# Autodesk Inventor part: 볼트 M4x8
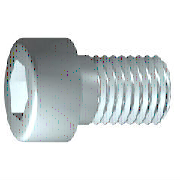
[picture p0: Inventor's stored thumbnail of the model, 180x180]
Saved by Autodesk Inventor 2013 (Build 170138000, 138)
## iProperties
Created: 2012-02
Part Number: 볼트 M4x8
Material: 스테인리스강
Description: 6각 소켓 머리 캡 나사
Document SubType Name: Modeling
Standard: ISO 4762
Designer: mduedu
Standard Revision: Fourth edition 2004-03-01
Standards Organization: ISO
Language: ko-KR
Size Designation: M4 x 8
Categories: <MemberInstance><Categories><Category DisplayName="조임쇠" InternalName="e4da775c-781d-43d5-af7c-5136215cf5a6" Mnemonic="FSTN"><Category DisplayName="볼트" InternalN
Density: 7.75 g/cm^3
Mass: 1.81382 g
Surface Area: 2.80587 cm^2
Volume: 0.234041 cm^3
IsCustomPart: 0
Author: mduedu
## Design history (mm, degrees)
sketch "스케치1"
  geometry: L1 (-1, 0)-(8, 0); L2 (8, 0)-(8, 2); L3 (8, 2)-(1.75, 2); L4 (1.75, 2)-(1.32, 2); L5 (1.32, 2)-(0, 2); L6 (0, 2)-(0, 3.5); L7 (0, 3.5)-(-4, 3.5); L8 (-4, 3.5)-(-4, 1.732); L9 (-4, 1.732)-(-2, 1.732); L10 (-2, 1.732)-(-1, 0); L11 (-6.4, 0)-(10.4, 0) reference; L12 (0, -0.7)-(0, 4.2) reference; L13 (1.75, 2)-(0, 2)
  constraints: 22 end point, 6 parallel, 2 collinear, 2 perpendicular, 1 horizontal, 1 point on line
  dimensions: "d1" = 6.25 distance from line of L3.end L2 (= GEL); "d2" = 0.42952 distance of L4.end L3.end (computed from GAL); "d3" = 4 distance between parallel lines of L8 L6 (= KOH); "d4" = 2 distance of L8.end L9.end (= INTI); "d5" = 60 deg angle of L10 L1; "d6" = 4 diameter of L3 L1 (= GD); "d7" = 4 diameter of L5 L1 (= BDM); "d8" = 3.4641 diameter of L9 L1 (= 1.1547 x SW); "d9" = 7 diameter of L7 L1 (= KOD); "d26" = 8 distance between parallel lines of L12 L2 (= NLG)
revolve "본체" sketch "스케치1" stored, may be unused: angle "d10" = 90 deg
sketch "스케치2"
  geometry: L1 (0, -4.9)-(0, 4.9) reference; L2 (-4.9, 0)-(4.9, 0) reference; L3 (1.732, 0)-(0.866, -1.5); L4 (0.866, -1.5)-(-0.866, -1.5); L5 (-0.866, -1.5)-(-1.732, 0); L6 (-1.732, 0)-(-0.866, 1.5); L7 (-0.866, 1.5)-(0.866, 1.5); L8 (0.866, 1.5)-(1.732, 0); 2 further points
  constraints: 12 end point, 1 coincident, 1 horizontal alignment, 1 point on line, 12 other
extrude "슬롯" join sketch "스케치2" stored distance "d11" = 10; taper "d12" = 0 deg
workplane "Work Plane1"
fillet "Fillet2" dims "d30" = 0.1 (= R)
body "Solid1"
fillet "모깎기1" dims "d17" = 0.4 (= RR)
feature "스레드" dims "d13" = 6.25 (= GEL), "d14" = 0
chamfer "모따기1" distance "d15" = 0.42941 (= -0.5 x SPD + 0.5 x GD); stored, may be unused: second distance "d16" = 0.42941 (= GUL), angle "d27" = 45 deg
other parameters: "GD" = 4 [user parameter; used in 2 equation terms], "NLG" = 8 [user parameter; used in 1 equation term], "GEL" = 6.25 [user parameter; used in 2 equation terms], "KOD" = 7 [user parameter; used in 1 equation term], "KOH" = 4 [user parameter; used in 1 equation term], "INTI" = 2 [user parameter; used in 1 equation term], "GAL" = 0.42941 (= 0.61345 x PTC) [user parameter; used in 1 equation term], "GUL" = 0.42941 (= 0.61345 x PTC) [user parameter; used in 1 equation term], "BDM" = 4 (= NND) [user parameter; used in 1 equation term], "SW" = 3 [user parameter; used in 2 equation terms], "RR" = 0.4 [user parameter; used in 1 equation term], "SPD" = 3.14117 (= NND - 1.2269 x PTC) [user parameter; used in 1 equation term], "d19" = 0, "d28" = 0, "d29" = 0, "R" = 0.1 [user parameter; used in 1 equation term], "TOA" = 30 deg [user parameter], "GD1" = 3.14117 (= THREADDIA - 1.2269 x PTC) [user parameter], "THREADDIA" = 4 [user parameter; used in 1 equation term], "FAWI" = 45 deg [user parameter], "TPU" = 14.28571 (computed from PTC) [user parameter], "PTC" = 0.7 [user parameter; used in 5 equation terms], "NND" = 4 [user parameter; used in 2 equation terms], "E0" = 3.465 (= 1.155 x SW) [user parameter]
